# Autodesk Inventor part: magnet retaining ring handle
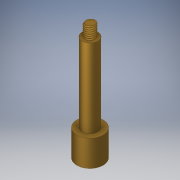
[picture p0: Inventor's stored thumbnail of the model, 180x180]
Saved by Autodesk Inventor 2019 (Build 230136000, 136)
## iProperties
Created: 2019-05
Part Number: magnet retaining ring handle
Material: Brass, Soft Yellow
Document SubType Name: Modeling
Designer: Chloe
Density: 8.47 g/cm^3
Appearance: Brass - Satin
Author: Chloe
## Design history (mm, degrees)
sketch "Sketch1"
  geometry: C1 r 5 at (0, 0); 1 further point
  constraints: 1 centre point, 1 coincident
  dimensions: "d0" = 10 diameter of C1
extrude "Extrusion1" new body sketch "Sketch1" distance "d1" = 10; taper "d2" = 0 deg
sketch "Sketch2"
  geometry: C1 r 3 at (0, 0); 1 further point
  constraints: 1 centre point, 1 coincident
  dimensions: "d3" = 6 diameter of C1
extrude "Extrusion2" join sketch "Sketch2" distance "d4" = 30; taper "d5" = 0 deg
sketch "Sketch3"
  geometry: C1 r 3 at (0, 0) reference; C2 r 1.919 at (0, 0); 1 further point
  constraints: 1 centre point, 1 coincident
  dimensions: "d6" = 3.838 diameter of C2
extrude "Extrusion3" join sketch "Sketch3" distance "d7" = 4.5; taper "d8" = 0 deg
thread "Thread1" dims "d9" = 25.4, "d10" = 0
sketch "Sketch8"
  geometry: L1 (1.919, 0)-(1.919, 4.5); L2 (1.919, 4.5)-(1.4, 4.5); L3 (1.4, 4.5)-(1.4, 0); L4 (1.4, 0)-(1.919, 0); L5 (0, -9.816)-(0, 53.553) reference
  constraints: 8 end point
revolve "Revolution3" sketch "Sketch8" stored, may be unused: angle "d39" = 0 deg
sketch "Sketch9"
  geometry: L1 (1.919, 0)-(1.919, 4.5); L2 (1.919, 4.5)-(1.4, 4.5); L3 (1.4, 4.5)-(1.4, 0); L4 (1.4, 0)-(1.919, 0); L5 (0, -9.816)-(0, 53.553) reference
  constraints: 8 end point
revolve "Revolution4" sketch "Sketch9" stored, may be unused: angle "d40" = 0 deg
sketch "Sketch7"
  geometry: L1 (-0.408, -1.436)-(-0.35, -1.436); L2 (0.058, -1.884)-(0, -1.996); L3 (-0.7, -1.996)-(-0.758, -1.884); L4 (-0.292, -1.436)-(-0.35, -1.323); L5 (-0.35, -1.323)-(-0.408, -1.436); L6 (-0.7, -1.996)-(-0.642, -1.884); L7 (-0.292, -1.436)-(-0.058, -1.884); L8 (-0.758, -1.884)-(-0.642, -1.884); L9 (0.058, -1.884)-(-0.058, -1.884); L10 (-0.7, -1.996)-(-0.7, -1.884); L11 (0, -1.996)-(0, -1.884); L12 (-0.35, -1.323)-(-0.35, -1.4); L13 (-0.7, -1.919)-(0, -1.919); L14 (-0.058, -1.884)-(0, -1.996); L15 (-0.642, -1.884)-(-0.408, -1.436); L16 (0, 0)-(0, 0.018); L17 (0, 0.018)-(0, 0); L18 (0, 0)-(0.033, 0); L19 (-0.35, -1.4)-(-0.35, -1.436); L20 (-0.35, -1.436)-(-0.292, -1.436); A1 r 0.066 centre (-0.7, -1.853) between (-0.758, -1.884) and (-0.7, -1.919); A2 r 0.066 centre (-0.7, -1.853) between (-0.7, -1.919) and (-0.642, -1.884); A3 r 0.066 centre (0, -1.853) between (-0.058, -1.884) and (0, -1.919); A4 r 0.066 centre (0, -1.853) between (0, -1.919) and (0.058, -1.884); A5 r 0.066 centre (-0.35, -1.466) between (-0.35, -1.4) and (-0.408, -1.436); A6 r 0.066 centre (-0.35, -1.466) between (-0.292, -1.436) and (-0.35, -1.4)
  constraints: 40 end point, 12 point on circle, 10 parallel, 8 tangent, 6 centre point, 6 collinear, 2 midpoint, 2 point on line, 1 horizontal, 1 perpendicular, 3 other
  dimensions: "d30" = 55 deg angle of L7 L15 (= d37); "d31" = 0.11206 distance of L4.end L1.end (= 0.160083 x Sketch7_Pitch); "d32" = 0.11206 distance of L2.end L11.end (= 0.160083 x Sketch7_Pitch); "Sketch7_ThreadOffset" = 0 distance between parallel lines of L16 L11; "Sketch7_MajorRadius" = 1.919 distance from line of L13 L16.start; "d35" = 0.7 distance from line of L2.end L10 (= Sketch7_Pitch); "Sketch7_MinorRadius" = 1.39998 distance edge to line of A6 L18 (derived)
coil "Coil2" sketch "Sketch7" pitch "d41" = 0.7007; turns "d43" = 1; dims "d42" = 5.9, "d44" = 0, angle "d45" = 0 deg, angle "d46" = 0 deg, "d47" = 0, "d48" = 0
body "Solid1"
body "Solid3"
other parameters: "d18" = 55 deg [user parameter], "Sketch4_Pitch" = 0.7 [user parameter], "d37" = 55 deg [user parameter; used in 1 equation term], "Sketch7_Pitch" = 0.7 [user parameter; used in 3 equation terms]
